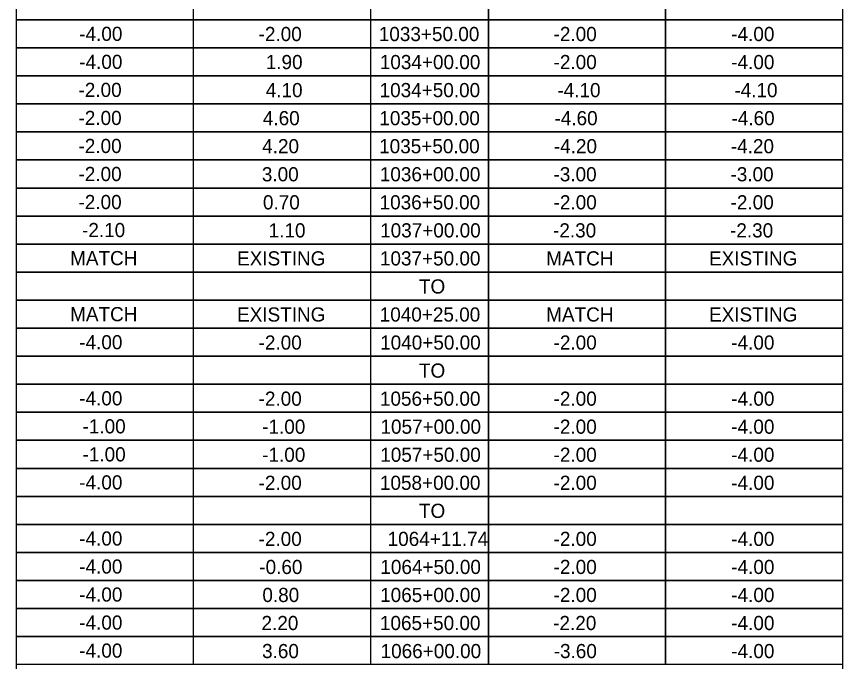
# Model space of a CAD drawing. Extents: x 1026502 to 1027102, y 781811 to 782040.
# Drawn here: x 1026655.03 to 1026683.03, y 781898.28 to 781920.14 of the extents above; entities that cross this region are included whole.
import ezdxf

# ---------------------------------------------------------------- set-up
doc = ezdxf.new("R2010")
doc.units = 0
for name, color, linetype in [('ANNOTATION', 7, 'Continuous'), ('BORDER', 7, 'Continuous'), ('DIMENSIONS', 7, 'Continuous')]:
    doc.layers.add(name, color=color, linetype=linetype)

msp = doc.modelspace()

# ---------------------------------------------------------------- linework, layer by layer
at = {"layer": 'ANNOTATION'}
msp.add_lwpolyline([(1026655.027, 781936.19), (1026683.027, 781936.19), (1026683.027, 781882.017), (1026655.027, 781882.017)], close=True, dxfattribs=at)
at = {"layer": 'BORDER'}
for p, q in [((1026658.027, 781920.033), (1026655.027, 781920.033)), ((1026658.027, 781920.033), (1026655.027, 781920.033)), ((1026658.027, 781920.033), (1026661.027, 781920.033)), ((1026658.027, 781919.082), (1026655.027, 781919.082)), ((1026658.027, 781919.082), (1026655.027, 781919.082)), ((1026658.027, 781919.082), (1026661.027, 781919.082)), ((1026658.027, 781918.132), (1026655.027, 781918.132)), ((1026658.027, 781918.132), (1026655.027, 781918.132)), ((1026658.027, 781918.132), (1026661.027, 781918.132)), ((1026658.027, 781917.182), (1026655.027, 781917.182)), ((1026658.027, 781917.182), (1026655.027, 781917.182)), ((1026658.027, 781917.182), (1026661.027, 781917.182)), ((1026658.027, 781916.231), (1026655.027, 781916.231)), ((1026658.027, 781916.231), (1026655.027, 781916.231)), ((1026658.027, 781916.231), (1026661.027, 781916.231)), ((1026658.027, 781915.281), (1026655.027, 781915.281)), ((1026658.027, 781915.281), (1026655.027, 781915.281)), ((1026658.027, 781915.281), (1026661.027, 781915.281)), ((1026658.027, 781914.33), (1026655.027, 781914.33)), ((1026658.027, 781914.33), (1026655.027, 781914.33)), ((1026658.027, 781914.33), (1026661.027, 781914.33)), ((1026658.027, 781913.38), (1026655.027, 781913.38)), ((1026658.027, 781913.38), (1026655.027, 781913.38)), ((1026658.027, 781913.38), (1026661.027, 781913.38)), ((1026658.027, 781912.43), (1026655.027, 781912.43)), ((1026658.027, 781912.43), (1026655.027, 781912.43)), ((1026658.027, 781912.43), (1026661.027, 781912.43)), ((1026658.027, 781911.479), (1026655.027, 781911.479)), ((1026658.027, 781911.479), (1026655.027, 781911.479)), ((1026658.027, 781911.479), (1026661.027, 781911.479)), ((1026658.027, 781910.529), (1026655.027, 781910.529)), ((1026658.027, 781910.529), (1026655.027, 781910.529)), ((1026658.027, 781910.529), (1026661.027, 781910.529)), ((1026658.027, 781909.578), (1026655.027, 781909.578)), ((1026658.027, 781909.578), (1026655.027, 781909.578)), ((1026658.027, 781909.578), (1026661.027, 781909.578)), ((1026658.027, 781908.628), (1026655.027, 781908.628)), ((1026658.027, 781908.628), (1026655.027, 781908.628)), ((1026658.027, 781908.628), (1026661.027, 781908.628)), ((1026658.027, 781907.678), (1026655.027, 781907.678)), ((1026658.027, 781907.678), (1026655.027, 781907.678)), ((1026658.027, 781907.678), (1026661.027, 781907.678)), ((1026658.027, 781906.727), (1026655.027, 781906.727)), ((1026658.027, 781906.727), (1026655.027, 781906.727)), ((1026658.027, 781906.727), (1026661.027, 781906.727)), ((1026658.027, 781905.777), (1026655.027, 781905.777)), ((1026658.027, 781905.777), (1026655.027, 781905.777)), ((1026658.027, 781905.777), (1026661.027, 781905.777)), ((1026658.027, 781904.826), (1026655.027, 781904.826)), ((1026658.027, 781904.826), (1026655.027, 781904.826)), ((1026658.027, 781904.826), (1026661.027, 781904.826)), ((1026658.027, 781903.876), (1026655.027, 781903.876)), ((1026658.027, 781903.876), (1026655.027, 781903.876)), ((1026658.027, 781903.876), (1026661.027, 781903.876)), ((1026658.027, 781902.926), (1026655.027, 781902.926)), ((1026658.027, 781902.926), (1026655.027, 781902.926)), ((1026658.027, 781902.926), (1026661.027, 781902.926)), ((1026658.027, 781901.975), (1026655.027, 781901.975)), ((1026658.027, 781901.975), (1026655.027, 781901.975)), ((1026658.027, 781901.975), (1026661.027, 781901.975)), ((1026658.027, 781901.025), (1026655.027, 781901.025)), ((1026658.027, 781901.025), (1026655.027, 781901.025)), ((1026658.027, 781901.025), (1026661.027, 781901.025)), ((1026658.027, 781900.074), (1026655.027, 781900.074)), ((1026658.027, 781900.074), (1026655.027, 781900.074)), ((1026658.027, 781900.074), (1026661.027, 781900.074)), ((1026658.027, 781899.124), (1026655.027, 781899.124)), ((1026658.027, 781899.124), (1026655.027, 781899.124)), ((1026658.027, 781899.124), (1026661.027, 781899.124))]:
    msp.add_line(p, q, dxfattribs=at)
for points in [[(1026655.027, 781920.983), (1026683.027, 781920.983), (1026683.027, 781920.033), (1026655.027, 781920.033)], [(1026655.027, 781920.033), (1026683.027, 781920.033), (1026683.027, 781919.082), (1026655.027, 781919.082)], [(1026655.027, 781919.082), (1026683.027, 781919.082), (1026683.027, 781918.132), (1026655.027, 781918.132)], [(1026655.027, 781918.132), (1026683.027, 781918.132), (1026683.027, 781917.182), (1026655.027, 781917.182)], [(1026655.027, 781917.182), (1026683.027, 781917.182), (1026683.027, 781916.231), (1026655.027, 781916.231)], [(1026655.027, 781916.231), (1026683.027, 781916.231), (1026683.027, 781915.281), (1026655.027, 781915.281)], [(1026655.027, 781915.281), (1026683.027, 781915.281), (1026683.027, 781914.33), (1026655.027, 781914.33)], [(1026655.027, 781914.33), (1026683.027, 781914.33), (1026683.027, 781913.38), (1026655.027, 781913.38)], [(1026655.027, 781913.38), (1026683.027, 781913.38), (1026683.027, 781912.43), (1026655.027, 781912.43)], [(1026655.027, 781912.43), (1026683.027, 781912.43), (1026683.027, 781911.479), (1026655.027, 781911.479)], [(1026655.027, 781911.479), (1026683.027, 781911.479), (1026683.027, 781910.529), (1026655.027, 781910.529)], [(1026655.027, 781910.529), (1026683.027, 781910.529), (1026683.027, 781909.578), (1026655.027, 781909.578)], [(1026655.027, 781909.578), (1026683.027, 781909.578), (1026683.027, 781908.628), (1026655.027, 781908.628)], [(1026655.027, 781908.628), (1026683.027, 781908.628), (1026683.027, 781907.678), (1026655.027, 781907.678)], [(1026655.027, 781907.678), (1026683.027, 781907.678), (1026683.027, 781906.727), (1026655.027, 781906.727)], [(1026655.027, 781906.727), (1026683.027, 781906.727), (1026683.027, 781905.777), (1026655.027, 781905.777)], [(1026655.027, 781905.777), (1026683.027, 781905.777), (1026683.027, 781904.826), (1026655.027, 781904.826)], [(1026655.027, 781904.826), (1026683.027, 781904.826), (1026683.027, 781903.876), (1026655.027, 781903.876)], [(1026655.027, 781903.876), (1026683.027, 781903.876), (1026683.027, 781902.926), (1026655.027, 781902.926)], [(1026655.027, 781902.926), (1026683.027, 781902.926), (1026683.027, 781901.975), (1026655.027, 781901.975)], [(1026655.027, 781901.975), (1026683.027, 781901.975), (1026683.027, 781901.025), (1026655.027, 781901.025)], [(1026655.027, 781901.025), (1026683.027, 781901.025), (1026683.027, 781900.074), (1026655.027, 781900.074)], [(1026655.027, 781900.074), (1026683.027, 781900.074), (1026683.027, 781899.124), (1026655.027, 781899.124)], [(1026655.027, 781899.124), (1026683.027, 781899.124), (1026683.027, 781898.174), (1026655.027, 781898.174)]]:
    msp.add_lwpolyline(points, close=True, dxfattribs=at)
for points in [[(1026667.027, 781920.983), (1026667.027, 781920.033), (1026661.027, 781920.033), (1026661.027, 781920.983)], [(1026671.027, 781920.983), (1026671.027, 781920.033), (1026667.027, 781920.033)], [(1026677.027, 781920.983), (1026677.027, 781920.033), (1026671.027, 781920.033), (1026671.027, 781920.983)], [(1026683.027, 781920.983), (1026683.027, 781920.033), (1026677.027, 781920.033), (1026677.027, 781920.983)], [(1026667.027, 781920.033), (1026667.027, 781919.082), (1026661.027, 781919.082), (1026661.027, 781920.033)], [(1026671.027, 781920.033), (1026671.027, 781919.082), (1026667.027, 781919.082)], [(1026677.027, 781920.033), (1026677.027, 781919.082), (1026671.027, 781919.082), (1026671.027, 781920.033)], [(1026683.027, 781920.033), (1026683.027, 781919.082), (1026677.027, 781919.082), (1026677.027, 781920.033)], [(1026667.027, 781919.082), (1026667.027, 781918.132), (1026661.027, 781918.132), (1026661.027, 781919.082)], [(1026671.027, 781919.082), (1026671.027, 781918.132), (1026667.027, 781918.132)], [(1026677.027, 781919.082), (1026677.027, 781918.132), (1026671.027, 781918.132), (1026671.027, 781919.082)], [(1026683.027, 781919.082), (1026683.027, 781918.132), (1026677.027, 781918.132), (1026677.027, 781919.082)], [(1026667.027, 781918.132), (1026667.027, 781917.182), (1026661.027, 781917.182), (1026661.027, 781918.132)], [(1026671.027, 781918.132), (1026671.027, 781917.182), (1026667.027, 781917.182)], [(1026677.027, 781918.132), (1026677.027, 781917.182), (1026671.027, 781917.182), (1026671.027, 781918.132)], [(1026683.027, 781918.132), (1026683.027, 781917.182), (1026677.027, 781917.182), (1026677.027, 781918.132)], [(1026667.027, 781917.182), (1026667.027, 781916.231), (1026661.027, 781916.231), (1026661.027, 781917.182)], [(1026671.027, 781917.182), (1026671.027, 781916.231), (1026667.027, 781916.231)], [(1026677.027, 781917.182), (1026677.027, 781916.231), (1026671.027, 781916.231), (1026671.027, 781917.182)], [(1026683.027, 781917.182), (1026683.027, 781916.231), (1026677.027, 781916.231), (1026677.027, 781917.182)], [(1026667.027, 781916.231), (1026667.027, 781915.281), (1026661.027, 781915.281), (1026661.027, 781916.231)], [(1026671.027, 781916.231), (1026671.027, 781915.281), (1026667.027, 781915.281)], [(1026677.027, 781916.231), (1026677.027, 781915.281), (1026671.027, 781915.281), (1026671.027, 781916.231)], [(1026683.027, 781916.231), (1026683.027, 781915.281), (1026677.027, 781915.281), (1026677.027, 781916.231)], [(1026667.027, 781915.281), (1026667.027, 781914.33), (1026661.027, 781914.33), (1026661.027, 781915.281)], [(1026671.027, 781915.281), (1026671.027, 781914.33), (1026667.027, 781914.33)], [(1026677.027, 781915.281), (1026677.027, 781914.33), (1026671.027, 781914.33), (1026671.027, 781915.281)], [(1026683.027, 781915.281), (1026683.027, 781914.33), (1026677.027, 781914.33), (1026677.027, 781915.281)], [(1026667.027, 781914.33), (1026667.027, 781913.38), (1026661.027, 781913.38), (1026661.027, 781914.33)], [(1026671.027, 781914.33), (1026671.027, 781913.38), (1026667.027, 781913.38)], [(1026677.027, 781914.33), (1026677.027, 781913.38), (1026671.027, 781913.38), (1026671.027, 781914.33)], [(1026683.027, 781914.33), (1026683.027, 781913.38), (1026677.027, 781913.38), (1026677.027, 781914.33)], [(1026667.027, 781913.38), (1026667.027, 781912.43), (1026661.027, 781912.43), (1026661.027, 781913.38)], [(1026671.027, 781913.38), (1026671.027, 781912.43), (1026667.027, 781912.43)], [(1026677.027, 781913.38), (1026677.027, 781912.43), (1026671.027, 781912.43), (1026671.027, 781913.38)], [(1026683.027, 781913.38), (1026683.027, 781912.43), (1026677.027, 781912.43), (1026677.027, 781913.38)], [(1026667.027, 781912.43), (1026667.027, 781911.479), (1026661.027, 781911.479), (1026661.027, 781912.43)], [(1026671.027, 781912.43), (1026671.027, 781911.479), (1026667.027, 781911.479)], [(1026677.027, 781912.43), (1026677.027, 781911.479), (1026671.027, 781911.479), (1026671.027, 781912.43)], [(1026683.027, 781912.43), (1026683.027, 781911.479), (1026677.027, 781911.479), (1026677.027, 781912.43)], [(1026667.027, 781911.479), (1026667.027, 781910.529), (1026661.027, 781910.529), (1026661.027, 781911.479)], [(1026671.027, 781911.479), (1026671.027, 781910.529), (1026667.027, 781910.529)], [(1026677.027, 781911.479), (1026677.027, 781910.529), (1026671.027, 781910.529), (1026671.027, 781911.479)], [(1026683.027, 781911.479), (1026683.027, 781910.529), (1026677.027, 781910.529), (1026677.027, 781911.479)], [(1026667.027, 781910.529), (1026667.027, 781909.578), (1026661.027, 781909.578), (1026661.027, 781910.529)], [(1026671.027, 781910.529), (1026671.027, 781909.578), (1026667.027, 781909.578)], [(1026677.027, 781910.529), (1026677.027, 781909.578), (1026671.027, 781909.578), (1026671.027, 781910.529)], [(1026683.027, 781910.529), (1026683.027, 781909.578), (1026677.027, 781909.578), (1026677.027, 781910.529)], [(1026667.027, 781909.578), (1026667.027, 781908.628), (1026661.027, 781908.628), (1026661.027, 781909.578)], [(1026671.027, 781909.578), (1026671.027, 781908.628), (1026667.027, 781908.628)], [(1026677.027, 781909.578), (1026677.027, 781908.628), (1026671.027, 781908.628), (1026671.027, 781909.578)], [(1026683.027, 781909.578), (1026683.027, 781908.628), (1026677.027, 781908.628), (1026677.027, 781909.578)], [(1026667.027, 781908.628), (1026667.027, 781907.678), (1026661.027, 781907.678), (1026661.027, 781908.628)], [(1026671.027, 781908.628), (1026671.027, 781907.678), (1026667.027, 781907.678)], [(1026677.027, 781908.628), (1026677.027, 781907.678), (1026671.027, 781907.678), (1026671.027, 781908.628)], [(1026683.027, 781908.628), (1026683.027, 781907.678), (1026677.027, 781907.678), (1026677.027, 781908.628)], [(1026667.027, 781907.678), (1026667.027, 781906.727), (1026661.027, 781906.727), (1026661.027, 781907.678)], [(1026671.027, 781907.678), (1026671.027, 781906.727), (1026667.027, 781906.727)], [(1026677.027, 781907.678), (1026677.027, 781906.727), (1026671.027, 781906.727), (1026671.027, 781907.678)], [(1026683.027, 781907.678), (1026683.027, 781906.727), (1026677.027, 781906.727), (1026677.027, 781907.678)], [(1026667.027, 781906.727), (1026667.027, 781905.777), (1026661.027, 781905.777), (1026661.027, 781906.727)], [(1026671.027, 781906.727), (1026671.027, 781905.777), (1026667.027, 781905.777)], [(1026677.027, 781906.727), (1026677.027, 781905.777), (1026671.027, 781905.777), (1026671.027, 781906.727)], [(1026683.027, 781906.727), (1026683.027, 781905.777), (1026677.027, 781905.777), (1026677.027, 781906.727)], [(1026667.027, 781905.777), (1026667.027, 781904.826), (1026661.027, 781904.826), (1026661.027, 781905.777)], [(1026671.027, 781905.777), (1026671.027, 781904.826), (1026667.027, 781904.826)], [(1026677.027, 781905.777), (1026677.027, 781904.826), (1026671.027, 781904.826), (1026671.027, 781905.777)], [(1026683.027, 781905.777), (1026683.027, 781904.826), (1026677.027, 781904.826), (1026677.027, 781905.777)], [(1026667.027, 781904.826), (1026667.027, 781903.876), (1026661.027, 781903.876), (1026661.027, 781904.826)], [(1026671.027, 781904.826), (1026671.027, 781903.876), (1026667.027, 781903.876)], [(1026677.027, 781904.826), (1026677.027, 781903.876), (1026671.027, 781903.876), (1026671.027, 781904.826)], [(1026683.027, 781904.826), (1026683.027, 781903.876), (1026677.027, 781903.876), (1026677.027, 781904.826)], [(1026667.027, 781903.876), (1026667.027, 781902.926), (1026661.027, 781902.926), (1026661.027, 781903.876)], [(1026671.027, 781903.876), (1026671.027, 781902.926), (1026667.027, 781902.926)], [(1026677.027, 781903.876), (1026677.027, 781902.926), (1026671.027, 781902.926), (1026671.027, 781903.876)], [(1026683.027, 781903.876), (1026683.027, 781902.926), (1026677.027, 781902.926), (1026677.027, 781903.876)], [(1026667.027, 781902.926), (1026667.027, 781901.975), (1026661.027, 781901.975), (1026661.027, 781902.926)], [(1026671.027, 781902.926), (1026671.027, 781901.975), (1026667.027, 781901.975)], [(1026677.027, 781902.926), (1026677.027, 781901.975), (1026671.027, 781901.975), (1026671.027, 781902.926)], [(1026683.027, 781902.926), (1026683.027, 781901.975), (1026677.027, 781901.975), (1026677.027, 781902.926)], [(1026667.027, 781901.975), (1026667.027, 781901.025), (1026661.027, 781901.025), (1026661.027, 781901.975)], [(1026671.027, 781901.975), (1026671.027, 781901.025), (1026667.027, 781901.025)], [(1026677.027, 781901.975), (1026677.027, 781901.025), (1026671.027, 781901.025), (1026671.027, 781901.975)], [(1026683.027, 781901.975), (1026683.027, 781901.025), (1026677.027, 781901.025), (1026677.027, 781901.975)], [(1026667.027, 781901.025), (1026667.027, 781900.074), (1026661.027, 781900.074), (1026661.027, 781901.025)], [(1026671.027, 781901.025), (1026671.027, 781900.074), (1026667.027, 781900.074)], [(1026677.027, 781901.025), (1026677.027, 781900.074), (1026671.027, 781900.074), (1026671.027, 781901.025)], [(1026683.027, 781901.025), (1026683.027, 781900.074), (1026677.027, 781900.074), (1026677.027, 781901.025)], [(1026667.027, 781900.074), (1026667.027, 781899.124), (1026661.027, 781899.124), (1026661.027, 781900.074)], [(1026671.027, 781900.074), (1026671.027, 781899.124), (1026667.027, 781899.124)], [(1026677.027, 781900.074), (1026677.027, 781899.124), (1026671.027, 781899.124), (1026671.027, 781900.074)], [(1026683.027, 781900.074), (1026683.027, 781899.124), (1026677.027, 781899.124), (1026677.027, 781900.074)], [(1026667.027, 781899.124), (1026667.027, 781898.174), (1026661.027, 781898.174), (1026661.027, 781899.124)], [(1026671.027, 781899.124), (1026671.027, 781898.174), (1026667.027, 781898.174)], [(1026677.027, 781899.124), (1026677.027, 781898.174), (1026671.027, 781898.174), (1026671.027, 781899.124)], [(1026683.027, 781899.124), (1026683.027, 781898.174), (1026677.027, 781898.174), (1026677.027, 781899.124)]]:
    msp.add_lwpolyline(points, dxfattribs=at)

# ---------------------------------------------------------------- texts
at = {"layer": 'DIMENSIONS'}
for s, p in [('-4.00', (1026657.154, 781919.318)), ('-2.00', (1026663.234, 781919.311)), ('1033+50.00', (1026667.308, 781919.311)), ('-2.00', (1026673.234, 781919.311)), ('-4.00', (1026679.257, 781919.311)), ('-4.00', (1026657.154, 781918.367)), ('1.90', (1026663.476, 781918.36)), ('1034+00.00', (1026667.342, 781918.36)), ('-2.00', (1026673.234, 781918.36)), ('-4.00', (1026679.257, 781918.36)), ('-2.00', (1026657.128, 781917.417)), ('4.10', (1026663.476, 781917.41)), ('1034+50.00', (1026667.335, 781917.41)), ('-4.10', (1026673.363, 781917.41)), ('-4.10', (1026679.363, 781917.41)), ('-2.00', (1026657.128, 781916.466)), ('4.60', (1026663.378, 781916.459)), ('1035+00.00', (1026667.327, 781916.459)), ('-4.60', (1026673.264, 781916.459)), ('-4.60', (1026679.264, 781916.459)), ('-2.00', (1026657.128, 781915.516)), ('4.20', (1026663.355, 781915.508)), ('1035+50.00', (1026667.32, 781915.508)), ('-4.20', (1026673.242, 781915.508)), ('-4.20', (1026679.242, 781915.508)), ('-2.00', (1026657.128, 781914.566)), ('3.00', (1026663.344, 781914.557)), ('1036+00.00', (1026667.342, 781914.557)), ('-3.00', (1026673.23, 781914.557)), ('-3.00', (1026679.23, 781914.557)), ('-2.00', (1026657.128, 781913.615)), ('0.70', (1026663.381, 781913.606)), ('1036+50.00', (1026667.335, 781913.606)), ('-2.00', (1026673.234, 781913.606)), ('-2.00', (1026679.234, 781913.606)), ('-2.10', (1026657.248, 781912.665)), ('1.10', (1026663.574, 781912.655)), ('1037+00.00', (1026667.354, 781912.655)), ('-2.30', (1026673.215, 781912.655)), ('-2.30', (1026679.215, 781912.655)), ('MATCH', (1026656.844, 781911.714)), ('EXISTING', (1026662.503, 781911.705)), ('1037+50.00', (1026667.346, 781911.705)), ('MATCH', (1026672.983, 781911.705)), ('EXISTING', (1026678.503, 781911.705)), ('TO', (1026668.669, 781910.754)), ('MATCH', (1026656.844, 781909.814)), ('EXISTING', (1026662.503, 781909.803)), ('1040+25.00', (1026667.339, 781909.803)), ('MATCH', (1026672.983, 781909.803)), ('EXISTING', (1026678.503, 781909.803)), ('-4.00', (1026657.154, 781908.863)), ('-2.00', (1026663.234, 781908.852)), ('1040+50.00', (1026667.354, 781908.852)), ('-2.00', (1026673.234, 781908.852)), ('-4.00', (1026679.257, 781908.852)), ('TO', (1026668.669, 781907.901)), ('-4.00', (1026657.154, 781906.962)), ('-2.00', (1026663.234, 781906.95)), ('1056+50.00', (1026667.346, 781906.95)), ('-2.00', (1026673.234, 781906.95)), ('-4.00', (1026679.257, 781906.95)), ('-1.00', (1026657.265, 781906.012)), ('-1.00', (1026663.355, 781906)), ('1057+00.00', (1026667.365, 781906)), ('-2.00', (1026673.234, 781906)), ('-4.00', (1026679.257, 781906)), ('-1.00', (1026657.265, 781905.062)), ('-1.00', (1026663.355, 781905.049)), ('1057+50.00', (1026667.357, 781905.049)), ('-2.00', (1026673.234, 781905.049)), ('-4.00', (1026679.257, 781905.049)), ('-4.00', (1026657.154, 781904.111)), ('-2.00', (1026663.234, 781904.098)), ('1058+00.00', (1026667.346, 781904.098)), ('-2.00', (1026673.234, 781904.098)), ('-4.00', (1026679.257, 781904.098)), ('TO', (1026668.669, 781903.147)), ('-4.00', (1026657.154, 781902.21)), ('-2.00', (1026663.234, 781902.196)), ('1064+11.74', (1026667.607, 781902.196)), ('-2.00', (1026673.234, 781902.196)), ('-4.00', (1026679.257, 781902.196)), ('-4.00', (1026657.154, 781901.26)), ('-0.60', (1026663.257, 781901.245)), ('1064+50.00', (1026667.361, 781901.245)), ('-2.00', (1026673.234, 781901.245)), ('-4.00', (1026679.257, 781901.245)), ('-4.00', (1026657.154, 781900.31)), ('0.80', (1026663.362, 781900.295)), ('1065+00.00', (1026667.354, 781900.295)), ('-2.00', (1026673.234, 781900.295)), ('-4.00', (1026679.257, 781900.295)), ('-4.00', (1026657.154, 781899.359)), ('2.20', (1026663.332, 781899.344)), ('1065+50.00', (1026667.346, 781899.344)), ('-2.20', (1026673.219, 781899.344)), ('-4.00', (1026679.257, 781899.344)), ('-4.00', (1026657.154, 781898.409)), ('3.60', (1026663.351, 781898.393)), ('1066+00.00', (1026667.369, 781898.393)), ('-3.60', (1026673.238, 781898.393)), ('-4.00', (1026679.257, 781898.393))]:
    msp.add_text(s, height=0.48, dxfattribs=at).set_placement(p)

doc.saveas('drawing.dxf')
